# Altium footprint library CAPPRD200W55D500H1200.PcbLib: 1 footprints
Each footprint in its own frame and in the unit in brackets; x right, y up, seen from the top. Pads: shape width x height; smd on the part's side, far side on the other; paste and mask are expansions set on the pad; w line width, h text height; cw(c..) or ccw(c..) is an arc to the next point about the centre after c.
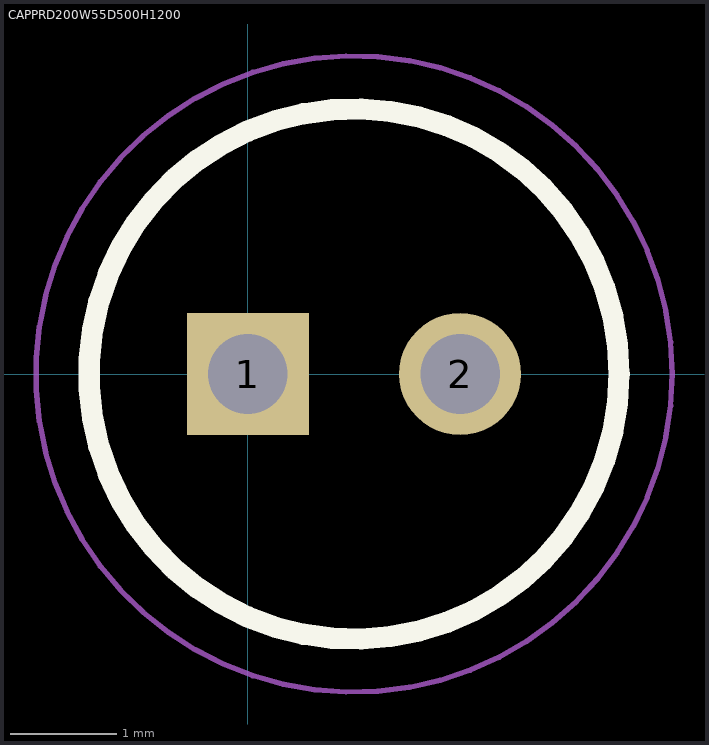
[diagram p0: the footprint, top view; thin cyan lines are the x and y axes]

## CAPPRD200W55D500H1200 [mm]
pads (2):
  rect 1.15x1.15 / inner round 1.15 / far side rect 1.15x1.15 hole 0.75: 1(0,0)
  round 1.15 hole 0.75: 2(2,0)
Top Overlay:
  circle w0.2: c1,0 r2.5
Mechanical 15:
  circle w0.1: c1,0 r2.5
Mechanical 20:
  circle w0.05: c1,0 r3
